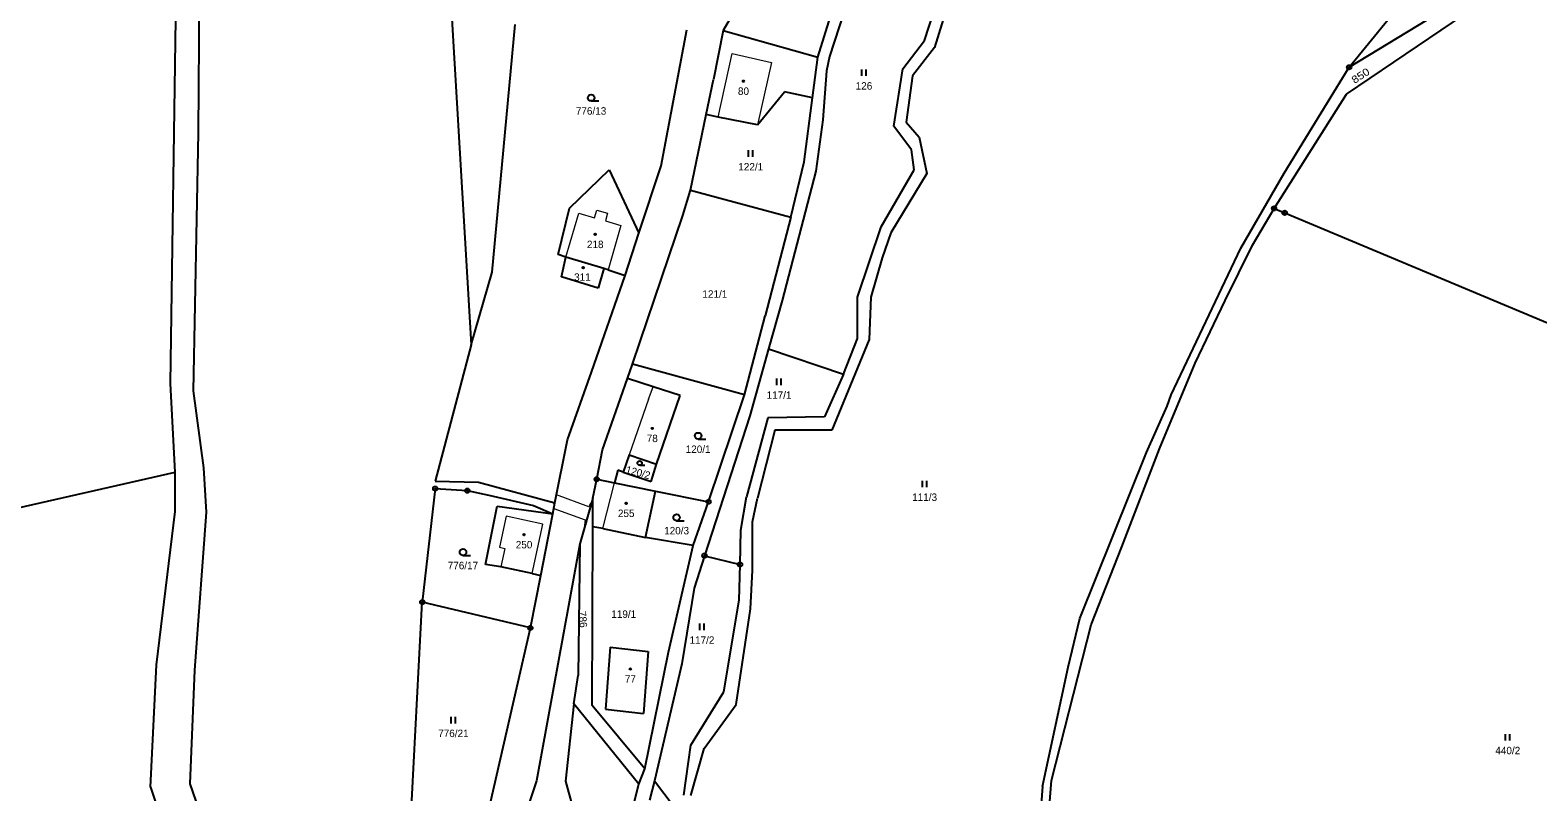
# Model space of a CAD drawing. Extents: x -739410 to -735662, y -942282 to -940043.
# Drawn here: x -737798.5 to -737454.1, y -941193.9 to -941020 of the extents above; entities that cross this region are included whole.
import ezdxf
from ezdxf.enums import TextEntityAlignment as Align

# ---------------------------------------------------------------- set-up
doc = ezdxf.new("R2010")
doc.units = 0
doc.header["$LTSCALE"] = 0.68
for name, color, linetype, lineweight in [('1', 7, 'Continuous', 25), ('13', 7, 'Continuous', 13), ('3', 7, 'Continuous', 25), ('4', 7, 'Continuous', 13), ('5', 7, 'Continuous', 25), ('8', 7, 'Continuous', 25)]:
    doc.layers.add(name, color=color, linetype=linetype, lineweight=lineweight)
doc.layers.add('2', color=7, linetype='Continuous')

msp = doc.modelspace()

# ---------------------------------------------------------------- linework, layer by layer
at = {"layer": '1'}
for p, q in [((-737705.67, -940957.52), (-737697.81, -941091.85)), ((-737766.44, -941100.66), (-737764.9, -940995.7)), ((-737628.63, -941000.17), (-737640.2, -941020.08)), ((-737497.2, -941028.46), (-737475.89, -941002.22)), ((-737618.6, -941026.13), (-737612.28, -941005.82)), ((-737760.05, -941043.44), (-737759.79, -941008.2)), ((-737610.28, -941008.69), (-737615.89, -941026.01)), ((-737497.2, -941028.46), (-737464.65, -941008.66)), ((-737594.23, -941022.36), (-737590.56, -941010.98)), ((-737588.6, -941013.17), (-737591.96, -941023.93)), ((-737497.77, -941034.63), (-737465.37, -941012.63)), ((-737693, -941075.26), (-737687.75, -941018.67)), ((-737654.41, -941050.98), (-737648.53, -941019.89)), ((-737640.2, -941020.08), (-737642.43, -941031.23)), ((-737640.2, -941020.08), (-737618.6, -941026.13)), ((-737599.13, -941028.8), (-737594.23, -941022.36)), ((-737619.82, -941035.42), (-737618.6, -941026.13)), ((-737615.89, -941026.01), (-737616.6, -941029.29)), ((-737591.96, -941023.93), (-737596.96, -941030.43)), ((-737616.6, -941029.29), (-737617.44, -941040.5)), ((-737601.2, -941041.95), (-737599.13, -941028.8)), ((-737596.96, -941030.43), (-737598.44, -941040.99)), ((-737512.05, -941052.62), (-737497.2, -941028.46)), ((-737644.09, -941039.25), (-737642.43, -941031.23)), ((-737632.35, -941041.64), (-737626.2, -941034.07)), ((-737619.82, -941035.42), (-737626.2, -941034.07)), ((-737621.69, -941050.05), (-737619.82, -941035.42)), ((-737514.36, -941060.69), (-737497.77, -941034.63)), ((-737647.65, -941056.5), (-737644.09, -941039.25)), ((-737641.32, -941039.82), (-737644.09, -941039.25)), ((-737632.35, -941041.64), (-737641.32, -941039.82)), ((-737617.44, -941040.5), (-737619.05, -941052.16)), ((-737761.2, -941102.34), (-737760.05, -941043.44)), ((-737597.2, -941047.31), (-737601.2, -941041.95)), ((-737598.44, -941040.99), (-737595.41, -941044.41)), ((-737596.56, -941051.88), (-737597.2, -941047.31)), ((-737595.41, -941044.41), (-737593.67, -941052.72)), ((-737659.44, -941066.35), (-737654.41, -941050.98)), ((-737624.72, -941062.69), (-737621.69, -941050.05)), ((-737675.28, -941060.64), (-737666.25, -941051.89)), ((-737666.25, -941051.89), (-737659.44, -941066.35)), ((-737619.05, -941052.16), (-737626.72, -941081.71)), ((-737604.1, -941064.87), (-737596.56, -941051.88)), ((-737593.67, -941052.72), (-737601.92, -941066.3)), ((-737521.91, -941069.75), (-737512.05, -941052.62)), ((-737649.39, -941062.33), (-737647.65, -941056.5)), ((-737647.65, -941056.5), (-737624.72, -941062.69)), ((-737677.87, -941071.26), (-737675.28, -941060.64)), ((-737519.26, -941069.12), (-737514.36, -941060.69)), ((-737514.36, -941060.69), (-737511.93, -941061.71)), ((-737659.17, -941091.11), (-737649.39, -941062.33)), ((-737624.72, -941062.69), (-737630.65, -941085.2)), ((-737609.51, -941080.98), (-737604.1, -941064.87)), ((-737511.93, -941061.71), (-737391.18, -941112.33)), ((-737662.61, -941076.01), (-737659.44, -941066.35)), ((-737601.92, -941066.3), (-737603.85, -941071.98)), ((-737676.15, -941071.83), (-737677.87, -941071.26)), ((-737667.48, -941074.39), (-737676.15, -941071.83)), ((-737537.83, -941103.26), (-737521.91, -941069.75)), ((-737525.49, -941081.73), (-737519.26, -941069.12)), ((-737697.81, -941091.85), (-737693, -941075.26)), ((-737667.48, -941074.39), (-737668.75, -941078.92)), ((-737666.52, -941074.69), (-737667.48, -941074.39)), ((-737666.52, -941074.69), (-737662.61, -941076.01)), ((-737603.85, -941071.98), (-737606.5, -941080.99)), ((-737670.29, -941098.08), (-737662.61, -941076.01)), ((-737626.72, -941081.71), (-737629.88, -941092.78)), ((-737609.51, -941090.4), (-737609.51, -941080.98)), ((-737606.5, -941080.99), (-737606.82, -941090.66)), ((-737532.36, -941096.06), (-737525.49, -941081.73)), ((-737635.36, -941103.3), (-737630.65, -941085.2)), ((-737697.81, -941091.85), (-737705.98, -941122.97)), ((-737660.94, -941096.29), (-737659.17, -941091.11)), ((-737606.82, -941090.66), (-737615.39, -941111.32)), ((-737612.73, -941098.52), (-737609.51, -941090.4)), ((-737629.88, -941092.78), (-737634.12, -941108.08)), ((-737629.88, -941092.78), (-737612.73, -941098.52)), ((-737540.56, -941115.58), (-737532.36, -941096.06)), ((-737675.79, -941113.56), (-737670.29, -941098.08)), ((-737662.08, -941099.56), (-737660.94, -941096.29)), ((-737635.36, -941103.3), (-737660.94, -941096.29)), ((-737612.73, -941098.52), (-737617.05, -941108.27)), ((-737765.42, -941120.92), (-737766.44, -941100.66)), ((-737758.89, -941119.95), (-737761.2, -941102.34)), ((-737667.76, -941115.83), (-737662.08, -941099.56)), ((-737656.24, -941101.45), (-737662.08, -941099.56)), ((-737650.03, -941103.45), (-737656.24, -941101.45)), ((-737655.44, -941119.13), (-737650.03, -941103.45)), ((-737643.55, -941127.7), (-737635.36, -941103.3)), ((-737543.51, -941116.47), (-737538.79, -941105.85)), ((-737538.79, -941105.85), (-737537.83, -941103.26)), ((-737634.12, -941108.08), (-737644.47, -941140.01)), ((-737630, -941108.53), (-737634.9, -941126.58)), ((-737617.05, -941108.27), (-737630, -941108.53)), ((-737628.39, -941111.38), (-737632.39, -941126.84)), ((-737615.39, -941111.32), (-737628.39, -941111.38)), ((-737678.63, -941127.95), (-737675.79, -941113.56)), ((-737669.09, -941122.56), (-737667.76, -941115.83)), ((-737558.71, -941154.37), (-737543.51, -941116.47)), ((-737549.16, -941138.01), (-737540.56, -941115.58)), ((-737758.25, -941130.04), (-737758.89, -941119.95)), ((-737661.68, -941116.99), (-737663.02, -941120.91)), ((-737661.68, -941116.99), (-737655.44, -941119.13)), ((-737656.69, -941123.08), (-737655.44, -941119.13)), ((-737857.78, -941141.94), (-737765.42, -941120.92)), ((-737765.42, -941129.89), (-737765.42, -941120.92)), ((-737705.98, -941122.97), (-737696.08, -941123.25)), ((-737696.08, -941123.25), (-737678.63, -941127.95)), ((-737669.95, -941126.89), (-737669.09, -941122.56)), ((-737669.09, -941122.56), (-737665.02, -941123.38)), ((-737664.27, -941120.49), (-737665.02, -941123.38)), ((-737665.02, -941123.38), (-737655.69, -941125.26)), ((-737663.02, -941120.91), (-737664.27, -941120.49)), ((-737663.02, -941120.91), (-737656.69, -941123.08)), ((-737706, -941124.7), (-737708.95, -941150.63)), ((-737706, -941124.7), (-737698.66, -941125.16)), ((-737698.66, -941125.16), (-737693.77, -941126.16)), ((-737693.77, -941126.16), (-737683.53, -941128.57)), ((-737669.95, -941126.89), (-737672.98, -941137.29)), ((-737669.98, -941133.43), (-737669.95, -941126.89)), ((-737657.97, -941135.85), (-737655.69, -941125.26)), ((-737655.69, -941125.26), (-737643.55, -941127.7)), ((-737636.18, -941134.15), (-737634.9, -941126.58)), ((-737633.52, -941132.3), (-737632.39, -941126.84)), ((-737769.64, -941164.97), (-737765.42, -941129.89)), ((-737760.94, -941166.14), (-737758.25, -941130.04)), ((-737694.48, -941142.05), (-737691.82, -941128.73)), ((-737691.82, -941128.73), (-737679.12, -941130.45)), ((-737683.53, -941128.57), (-737679.12, -941130.45)), ((-737681.89, -941144.54), (-737679.12, -941130.45)), ((-737679.12, -941130.45), (-737678.63, -941127.95)), ((-737647.05, -941137.65), (-737643.55, -941127.7)), ((-737670.14, -941174.25), (-737669.98, -941133.43)), ((-737667.73, -941133.84), (-737669.98, -941133.43)), ((-737667.73, -941133.84), (-737657.97, -941135.85)), ((-737633.52, -941143.37), (-737633.52, -941132.3)), ((-737672.98, -941137.29), (-737682.83, -941191.42)), ((-737672.98, -941137.29), (-737673.36, -941167.38)), ((-737647.05, -941137.65), (-737657.97, -941135.85)), ((-737636.35, -941142.03), (-737636.18, -941134.15)), ((-737652.67, -941162.02), (-737647.05, -941137.65)), ((-737644.47, -941140.01), (-737646.87, -941147.42)), ((-737644.47, -941140.01), (-737636.35, -941142.03)), ((-737556.15, -941155.82), (-737549.16, -941138.01)), ((-737690.97, -941142.55), (-737694.48, -941142.05)), ((-737683.83, -941144.07), (-737690.97, -941142.55)), ((-737683.83, -941144.07), (-737681.89, -941144.54)), ((-737636.52, -941150.17), (-737636.35, -941142.03)), ((-737633.95, -941152.16), (-737633.52, -941143.37)), ((-737684.24, -941156.52), (-737681.89, -941144.54)), ((-737646.87, -941147.42), (-737649.68, -941164.72)), ((-737713.04, -941229.19), (-737708.95, -941150.63)), ((-737684.24, -941156.52), (-737708.95, -941150.63)), ((-737640.04, -941171.08), (-737636.52, -941150.17)), ((-737637.21, -941173.99), (-737633.95, -941152.16)), ((-737561.41, -941165.5), (-737558.71, -941154.37)), ((-737694.22, -941200.05), (-737684.24, -941156.52)), ((-737565.18, -941191.33), (-737556.15, -941155.82)), ((-737666.06, -941160.92), (-737667.08, -941175.05)), ((-737666.06, -941160.92), (-737657.37, -941161.9)), ((-737657.37, -941161.9), (-737658.39, -941176.03)), ((-737658.09, -941188.7), (-737652.67, -941162.02)), ((-737649.68, -941164.72), (-737655.9, -941191.46)), ((-737771.05, -941192.85), (-737769.64, -941164.97)), ((-737761.97, -941192.13), (-737760.94, -941166.14)), ((-737674.33, -941173.86), (-737673.36, -941167.38)), ((-737567.25, -941192.75), (-737561.41, -941165.5)), ((-737647.61, -941183.26), (-737640.04, -941171.08)), ((-737674.33, -941173.86), (-737676.2, -941191.53)), ((-737659.51, -941192.23), (-737674.33, -941173.86)), ((-737658.09, -941188.7), (-737670.14, -941174.25)), ((-737667.08, -941175.05), (-737658.39, -941176.03)), ((-737644.58, -941184.02), (-737637.21, -941173.99)), ((-737649.18, -941194.7), (-737647.61, -941183.26)), ((-737647.62, -941194.77), (-737644.58, -941184.02)), ((-737659.51, -941192.23), (-737658.09, -941188.7)), ((-737756.97, -941206.68), (-737761.97, -941192.13)), ((-737682.83, -941191.42), (-737690.64, -941214.57)), ((-737676.2, -941191.53), (-737672.85, -941203.76)), ((-737664.47, -941211.81), (-737659.51, -941192.23)), ((-737655.9, -941191.46), (-737657.03, -941195.88)), ((-737655.9, -941191.46), (-737649.49, -941199.91)), ((-737566.68, -941209.91), (-737565.18, -941191.33)), ((-737771.05, -941192.85), (-737767.91, -941202.23)), ((-737567.25, -941192.75), (-737568.89, -941215.34))]:
    msp.add_line(p, q, dxfattribs=at)
msp.add_lwpolyline([(-737668.75, -941078.92), (-737677.18, -941076.33), (-737676.15, -941071.83)], dxfattribs=at)
at = {"layer": '13'}
msp.add_lwpolyline([(-737678.27, -941126.14), (-737678.63, -941127.95), (-737678.88, -941129.22), (-737671.77, -941131.83), (-737671.94, -941133.7), (-737670.32, -941128.16), (-737670.51, -941128.05), (-737670.93, -941128.83)], close=True, dxfattribs=at)
at = {"layer": '3'}
for p, q in [((-737608.551, -941030.44), (-737608.551, -941028.94)), ((-737607.55, -941030.44), (-737607.55, -941028.94)), ((-737670.383, -941036.16), (-737668.633, -941036.16)), ((-737634.421, -941048.91), (-737634.421, -941047.41)), ((-737633.42, -941048.91), (-737633.42, -941047.41)), ((-737627.951, -941101.06), (-737627.951, -941099.56)), ((-737626.95, -941101.06), (-737626.95, -941099.56)), ((-737645.923, -941113.42), (-737644.173, -941113.42)), ((-737659.285, -941119.37), (-737658.113, -941119.37)), ((-737594.691, -941124.38), (-737594.691, -941122.88)), ((-737593.69, -941124.38), (-737593.69, -941122.88)), ((-737650.843, -941132.02), (-737649.093, -941132.02)), ((-737699.653, -941139.98), (-737697.903, -941139.98)), ((-737645.571, -941157.02), (-737645.571, -941155.52)), ((-737644.57, -941157.02), (-737644.57, -941155.52)), ((-737702.351, -941178.32), (-737702.351, -941176.82)), ((-737701.35, -941178.32), (-737701.35, -941176.82)), ((-737461.471, -941182.24), (-737461.471, -941180.74)), ((-737460.47, -941182.24), (-737460.47, -941180.74))]:
    msp.add_line(p, q, dxfattribs=at)
for centre, radius in [((-737670.3829, -941035.4098), 0.75), ((-737645.9229, -941112.6698), 0.75), ((-737659.2852, -941118.8674), 0.5025), ((-737650.8429, -941131.2698), 0.75), ((-737699.6529, -941139.2298), 0.75)]:
    msp.add_circle(centre, radius, dxfattribs=at)
at = {"layer": '4'}
for p, q in [((-737629.2, -941027.38), (-737632.35, -941041.64)), ((-737669.57, -941062.85), (-737669.09, -941061.13)), ((-737669.09, -941061.13), (-737666.64, -941061.81)), ((-737676.15, -941071.83), (-737673.21, -941061.79)), ((-737673.21, -941061.79), (-737669.57, -941062.85)), ((-737666.64, -941061.81), (-737667.13, -941063.56)), ((-737667.13, -941063.56), (-737663.59, -941064.62)), ((-737663.59, -941064.62), (-737666.52, -941074.69)), ((-737657.27, -941104.23), (-737656.24, -941101.45)), ((-737657.27, -941104.23), (-737661.68, -941116.99)), ((-737667.73, -941133.84), (-737665.02, -941123.38)), ((-737689.79, -941130.99), (-737691.33, -941138.07)), ((-737681.39, -941132.81), (-737689.79, -941130.99)), ((-737683.83, -941144.07), (-737681.39, -941132.81)), ((-737691.33, -941138.07), (-737690.06, -941138.35)), ((-737690.06, -941138.35), (-737690.97, -941142.55))]:
    msp.add_line(p, q, dxfattribs=at)
msp.add_lwpolyline([(-737641.32, -941039.82), (-737638.12, -941025.35), (-737629.2, -941027.38)], dxfattribs=at)
at = {"layer": '5'}
for centre in [(-737635.5768, -941031.6392), (-737669.4468, -941066.6392), (-737672.1868, -941074.2392), (-737656.4168, -941110.9492), (-737662.3668, -941128.0592), (-737685.7068, -941135.2192), (-737661.4068, -941165.8792)]:
    msp.add_circle(centre, 0.175, dxfattribs=at)
at = {"layer": '8'}
for centre, radius in [((-737497.2, -941028.4599), 0.5), ((-737497.2, -941028.4599), 0.0303), ((-737514.36, -941060.6899), 0.5), ((-737514.36, -941060.6899), 0.0303), ((-737511.93, -941061.7099), 0.5), ((-737511.93, -941061.7099), 0.0303), ((-737669.09, -941122.5599), 0.5), ((-737669.09, -941122.5599), 0.0303), ((-737706, -941124.6999), 0.5), ((-737706, -941124.6999), 0.0303), ((-737698.66, -941125.1599), 0.5), ((-737698.66, -941125.1599), 0.0303), ((-737643.55, -941127.6999), 0.5), ((-737643.55, -941127.6999), 0.0303), ((-737644.47, -941140.0099), 0.5), ((-737644.47, -941140.0099), 0.0303), ((-737636.35, -941142.0299), 0.5), ((-737636.35, -941142.0299), 0.0303), ((-737708.95, -941150.6299), 0.5), ((-737708.95, -941150.6299), 0.0303), ((-737684.24, -941156.5199), 0.5), ((-737684.24, -941156.5199), 0.0303)]:
    msp.add_circle(centre, radius, dxfattribs=at)

# ---------------------------------------------------------------- texts
at = {"layer": '2', "width": 1.15}
msp.add_text('850', height=1.7, rotation=33, dxfattribs=at).set_placement((-737494.1324, -941031.0931), align=Align.CENTER)
at = {"layer": '2'}
for s, p in [('80', (-737635.569, -941034.765)), ('126', (-737608.039, -941033.565)), ('776/13', (-737670.39, -941039.285)), ('122/1', (-737633.91, -941052.035)), ('218', (-737669.439, -941069.765)), ('121/1', (-737642.11, -941081.095)), ('117/1', (-737627.44, -941104.185)), ('78', (-737656.409, -941114.075)), ('120/1', (-737645.93, -941116.545)), ('111/3', (-737594.18, -941127.505)), ('255', (-737662.359, -941131.185)), ('120/3', (-737650.85, -941135.145)), ('250', (-737685.699, -941138.345)), ('776/17', (-737699.66, -941143.105)), ('119/1', (-737662.93, -941154.215)), ('117/2', (-737645.06, -941160.145)), ('77', (-737661.399, -941169.005)), ('776/21', (-737701.84, -941181.445)), ('440/2', (-737460.96, -941185.365))]:
    msp.add_text(s, height=1.7, dxfattribs=at).set_placement(p, align=Align.CENTER)
msp.add_text('311', height=1.7, dxfattribs=at).set_placement((-737674.26, -941077.235))
for s, rotation, p in [('120/2', 345, (-737659.868, -941121.8399)), ('786', 275, (-737673.0999, -941154.6244))]:
    msp.add_text(s, height=1.7, rotation=rotation, dxfattribs=at).set_placement(p, align=Align.CENTER)

doc.saveas('drawing.dxf')
